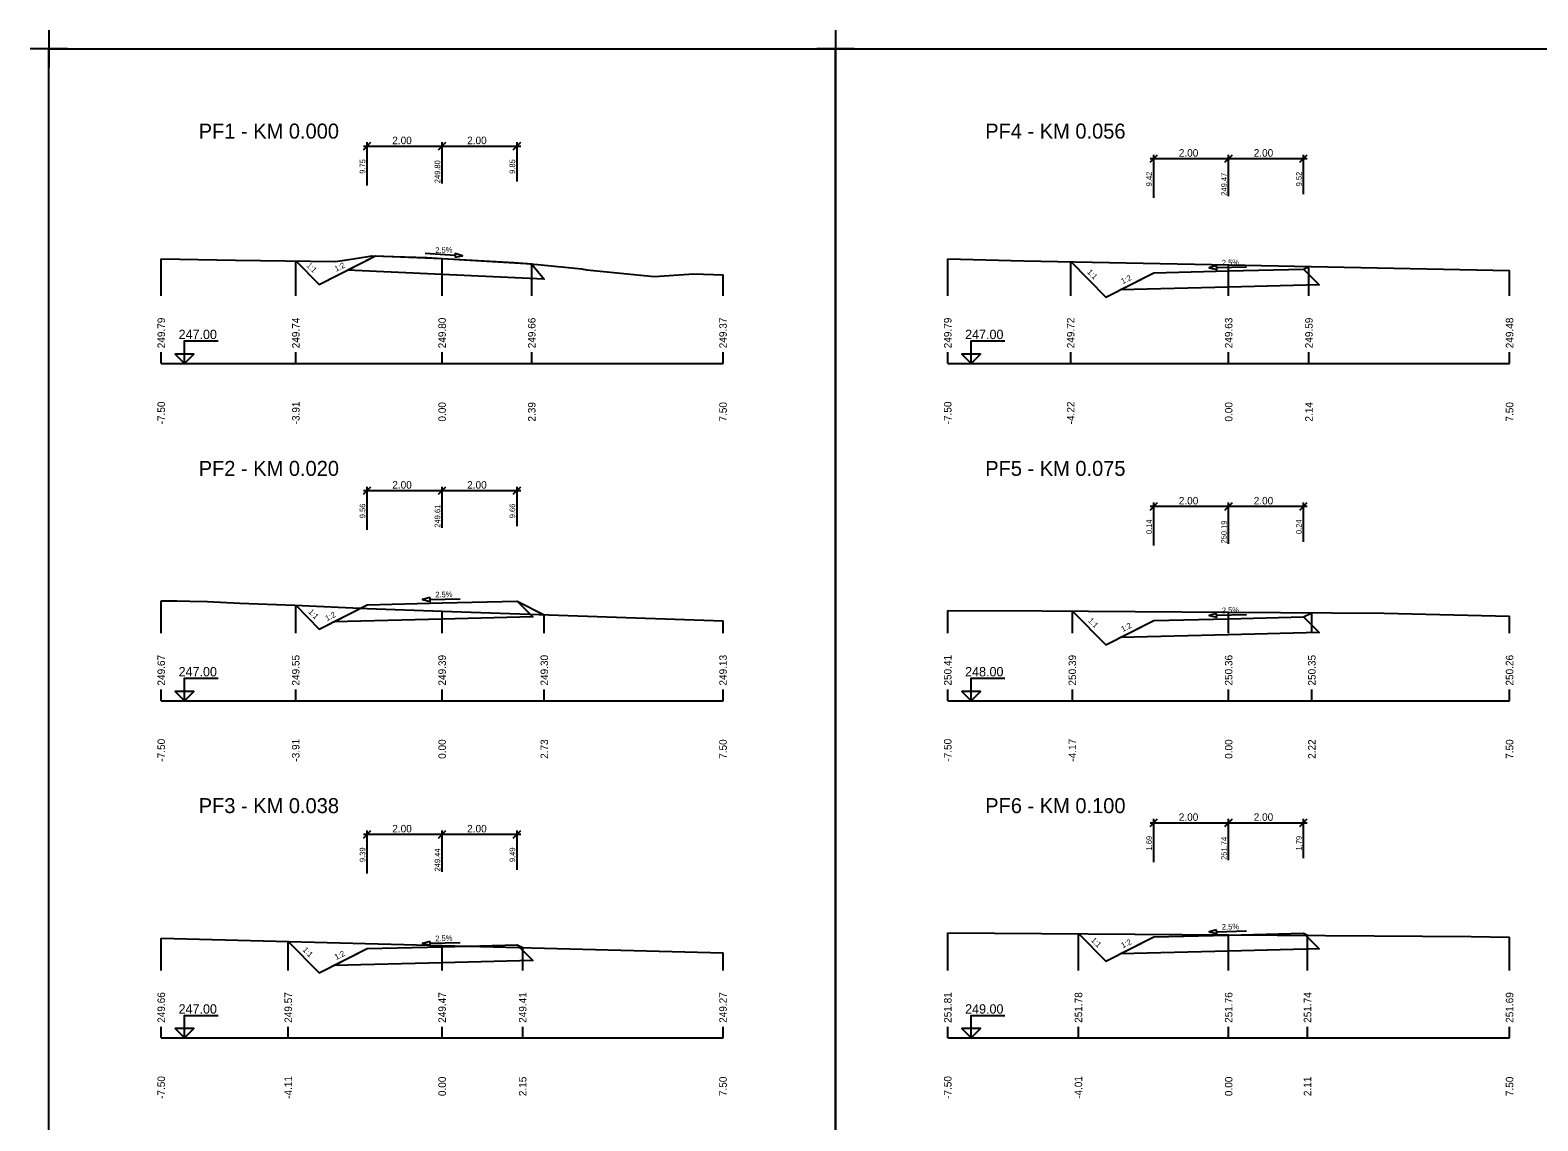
# Model space of a CAD drawing. Extents: x -1895 to 2525, y -19 to 585.
# Drawn here: x -1894.9 to -1492.4, y 293.9 to 584.9 of the extents above; entities that cross this region are included whole.
import ezdxf

# ---------------------------------------------------------------- set-up
doc = ezdxf.new("R2010")
doc.units = 0
for name, color, linetype in [('KOTA', 7, 'Continuous'), ('KOTA_DELKY', 7, 'Continuous'), ('KOTA_DELKY_CONT', 7, 'Continuous'), ('NS_TELESO_VOZOVKY', 7, 'Continuous'), ('NS_V_PF', 7, 'Continuous'), ('REZY_PF_PUVODNI', 7, 'Continuous'), ('SESTAVY_REZU_PF', 7, 'Continuous'), ('SKLON', 7, 'Continuous'), ('SVK', 7, 'Continuous')]:
    doc.layers.add(name, color=color, linetype=linetype)

msp = doc.modelspace()

# ---------------------------------------------------------------- linework, layer by layer
for p, q in [((-1889.95, 584.93), (-1889.95, 574.93)), ((-1889.95, 584.93), (-1889.95, 574.93)), ((-1679.95, 584.93), (-1679.95, 574.93)), ((-1679.95, 584.93), (-1679.95, 574.93)), ((-1884.95, 579.93), (-1894.95, 579.93)), ((-1884.95, 579.93), (-1894.95, 579.93)), ((-1674.95, 579.93), (-1684.95, 579.93)), ((-1674.95, 579.93), (-1684.95, 579.93))]:
    msp.add_line(p, q)
for points in [[(-1889.95, 579.93), (-1679.95, 579.93), (-1679.95, 282.93), (-1889.95, 282.93)], [(-1679.95, 579.93), (-1469.95, 579.93), (-1469.95, 282.93), (-1679.95, 282.93)]]:
    msp.add_lwpolyline(points, close=True)
at = {"layer": 'KOTA'}
for points in [[(-1853.73, 498.5), (-1856.23, 498.5), (-1853.73, 496), (-1853.73, 502), (-1844.73, 502)], [(-1643.73, 498.5), (-1646.23, 498.5), (-1643.73, 496), (-1643.73, 502), (-1634.73, 502)], [(-1853.73, 496), (-1851.23, 498.5), (-1853.73, 498.5)], [(-1643.73, 496), (-1641.23, 498.5), (-1643.73, 498.5)], [(-1853.73, 408.5), (-1856.23, 408.5), (-1853.73, 406), (-1853.73, 412), (-1844.73, 412)], [(-1643.73, 408.5), (-1646.23, 408.5), (-1643.73, 406), (-1643.73, 412), (-1634.73, 412)], [(-1853.73, 406), (-1851.23, 408.5), (-1853.73, 408.5)], [(-1643.73, 406), (-1641.23, 408.5), (-1643.73, 408.5)], [(-1853.73, 318.5), (-1856.23, 318.5), (-1853.73, 316), (-1853.73, 322), (-1844.73, 322)], [(-1853.73, 316), (-1851.23, 318.5), (-1853.73, 318.5)], [(-1643.73, 318.5), (-1646.23, 318.5), (-1643.73, 316), (-1643.73, 322), (-1634.73, 322)], [(-1643.73, 316), (-1641.23, 318.5), (-1643.73, 318.5)]]:
    msp.add_lwpolyline(points, dxfattribs=at)
at = {"layer": 'KOTA_DELKY'}
for points in [[(-1805.95, 553.01), (-1803.95, 555.01)], [(-1805.95, 554.01), (-1783.95, 554.01)], [(-1804.95, 543.51), (-1804.95, 555.01)], [(-1785.95, 553.01), (-1783.95, 555.01)], [(-1785.95, 553.01), (-1783.95, 555.01)], [(-1785.95, 554.01), (-1763.95, 554.01)], [(-1784.95, 544.01), (-1784.95, 555.01)], [(-1784.95, 544.01), (-1784.95, 555.01)], [(-1765.95, 553.01), (-1763.95, 555.01)], [(-1764.95, 544.51), (-1764.95, 555.01)], [(-1595.95, 549.68), (-1593.95, 551.68)], [(-1594.95, 540.18), (-1594.95, 551.68)], [(-1575.95, 549.68), (-1573.95, 551.68)], [(-1575.95, 549.68), (-1573.95, 551.68)], [(-1574.95, 540.68), (-1574.95, 551.68)], [(-1574.95, 540.68), (-1574.95, 551.68)], [(-1555.95, 549.68), (-1553.95, 551.68)], [(-1554.95, 541.18), (-1554.95, 551.68)], [(-1595.95, 550.68), (-1573.95, 550.68)], [(-1575.95, 550.68), (-1553.95, 550.68)], [(-1805.95, 461.1), (-1803.95, 463.1)], [(-1804.95, 451.6), (-1804.95, 463.1)], [(-1785.95, 461.1), (-1783.95, 463.1)], [(-1785.95, 461.1), (-1783.95, 463.1)], [(-1784.95, 452.1), (-1784.95, 463.1)], [(-1784.95, 452.1), (-1784.95, 463.1)], [(-1765.95, 461.1), (-1763.95, 463.1)], [(-1764.95, 452.6), (-1764.95, 463.1)], [(-1805.95, 462.1), (-1783.95, 462.1)], [(-1785.95, 462.1), (-1763.95, 462.1)], [(-1595.95, 456.88), (-1593.95, 458.88)], [(-1595.95, 457.88), (-1573.95, 457.88)], [(-1594.95, 447.38), (-1594.95, 458.88)], [(-1575.95, 456.88), (-1573.95, 458.88)], [(-1575.95, 456.88), (-1573.95, 458.88)], [(-1575.95, 457.88), (-1553.95, 457.88)], [(-1574.95, 447.88), (-1574.95, 458.88)], [(-1574.95, 447.88), (-1574.95, 458.88)], [(-1555.95, 456.88), (-1553.95, 458.88)], [(-1554.95, 448.38), (-1554.95, 458.88)], [(-1595.95, 372.45), (-1593.95, 374.45)], [(-1594.95, 362.95), (-1594.95, 374.45)], [(-1575.95, 372.45), (-1573.95, 374.45)], [(-1575.95, 372.45), (-1573.95, 374.45)], [(-1574.95, 363.45), (-1574.95, 374.45)], [(-1574.95, 363.45), (-1574.95, 374.45)], [(-1555.95, 372.45), (-1553.95, 374.45)], [(-1554.95, 363.95), (-1554.95, 374.45)], [(-1805.95, 369.36), (-1803.95, 371.36)], [(-1805.95, 370.36), (-1783.95, 370.36)], [(-1804.95, 359.86), (-1804.95, 371.36)], [(-1785.95, 369.36), (-1783.95, 371.36)], [(-1785.95, 369.36), (-1783.95, 371.36)], [(-1785.95, 370.36), (-1763.95, 370.36)], [(-1784.95, 360.36), (-1784.95, 371.36)], [(-1784.95, 360.36), (-1784.95, 371.36)], [(-1765.95, 369.36), (-1763.95, 371.36)], [(-1764.95, 360.86), (-1764.95, 371.36)], [(-1595.95, 373.45), (-1573.95, 373.45)], [(-1575.95, 373.45), (-1553.95, 373.45)]]:
    msp.add_lwpolyline(points, dxfattribs=at)
at = {"layer": 'NS_TELESO_VOZOVKY'}
for points in [[(-1784.95, 524.01), (-1761.06, 522.58), (-1761.06, 522.58), (-1757.74, 518.46), (-1784.95, 519.71), (-1810.25, 520.86), (-1802.75, 524.69), (-1802.75, 524.69), (-1784.95, 524.01)], [(-1574.95, 520.68), (-1554.95, 521.18), (-1554.95, 521.18), (-1550.75, 516.98), (-1574.95, 516.38), (-1603.89, 515.65), (-1594.95, 520.18), (-1594.95, 520.18), (-1574.95, 520.68)], [(-1784.95, 432.1), (-1764.95, 432.6), (-1764.95, 432.6), (-1760.75, 428.4), (-1784.95, 427.8), (-1813.89, 427.08), (-1804.95, 431.6), (-1804.95, 431.6), (-1784.95, 432.1)], [(-1574.95, 427.88), (-1554.95, 428.38), (-1554.95, 428.38), (-1550.75, 424.19), (-1574.95, 423.58), (-1603.89, 422.86), (-1594.95, 427.38), (-1594.95, 427.38), (-1574.95, 427.88)], [(-1574.95, 343.45), (-1554.95, 343.95), (-1554.95, 343.95), (-1550.75, 339.75), (-1574.95, 339.15), (-1603.89, 338.43), (-1594.95, 342.95), (-1594.95, 342.95), (-1574.95, 343.45)], [(-1784.95, 340.36), (-1764.95, 340.86), (-1764.95, 340.86), (-1760.75, 336.66), (-1784.95, 336.06), (-1813.89, 335.34), (-1804.95, 339.86), (-1804.95, 339.86), (-1784.95, 340.36)]]:
    msp.add_lwpolyline(points, dxfattribs=at)
at = {"layer": 'NS_V_PF'}
for points in [[(-1824.01, 523.35), (-1817.76, 517.04), (-1802.75, 524.69), (-1802.75, 524.69), (-1784.95, 524.01), (-1765.74, 522.97), (-1765.74, 522.97), (-1761.02, 522.55)], [(-1617.13, 523.17), (-1607.76, 513.7), (-1594.95, 520.18), (-1594.95, 520.18), (-1574.95, 520.68), (-1554.95, 521.18), (-1554.95, 521.18), (-1553.52, 521.89)], [(-1824.04, 431.46), (-1817.76, 425.12), (-1804.95, 431.6), (-1804.95, 431.6), (-1784.95, 432.1), (-1764.95, 432.6), (-1764.95, 432.6), (-1757.67, 428.96)], [(-1616.69, 429.93), (-1607.76, 420.9), (-1594.95, 427.38), (-1594.95, 427.38), (-1574.95, 427.88), (-1554.95, 428.38), (-1554.95, 428.38), (-1552.74, 429.49)], [(-1615.06, 343.84), (-1607.76, 336.47), (-1594.95, 342.95), (-1594.95, 342.95), (-1574.95, 343.45), (-1554.95, 343.95), (-1554.95, 343.95), (-1553.89, 343.42)], [(-1826.04, 341.75), (-1817.76, 333.38), (-1804.95, 339.86), (-1804.95, 339.86), (-1784.95, 340.36), (-1764.95, 340.86), (-1764.95, 340.86), (-1763.44, 340.11)]]:
    msp.add_lwpolyline(points, dxfattribs=at)
at = {"layer": 'REZY_PF_PUVODNI'}
for points in [[(-1859.95, 523.88), (-1840.11, 523.52), (-1813.43, 523.24), (-1808.08, 523.99), (-1803.74, 524.74), (-1789.08, 524.24), (-1784.95, 524.01), (-1765.74, 522.97), (-1759.43, 522.41), (-1747.75, 521.26), (-1746.32, 521.01), (-1728.38, 519.24), (-1717.72, 519.9), (-1709.95, 519.67)], [(-1649.95, 523.92), (-1629.68, 523.42), (-1574.95, 522.32), (-1499.95, 520.82)], [(-1859.95, 432.68), (-1855.79, 432.61), (-1852.29, 432.53), (-1847.59, 432.45), (-1838.96, 432.04), (-1824.3, 431.48), (-1804.93, 430.62), (-1784.95, 429.92), (-1709.95, 427.28)], [(-1649.95, 430.07), (-1624.86, 429.99), (-1574.95, 429.64), (-1533.46, 429.35), (-1499.95, 428.59)], [(-1859.95, 342.64), (-1784.95, 340.67), (-1709.95, 338.7)], [(-1649.95, 344.09), (-1574.95, 343.57), (-1510.19, 343.12), (-1499.95, 342.89)]]:
    msp.add_lwpolyline(points, dxfattribs=at)
at = {"layer": 'SESTAVY_REZU_PF'}
for points in [[(-1859.95, 496), (-1709.95, 496)], [(-1649.95, 496), (-1499.95, 496)], [(-1859.95, 406), (-1709.95, 406)], [(-1649.95, 406), (-1499.95, 406)], [(-1859.95, 316), (-1709.95, 316)], [(-1649.95, 316), (-1499.95, 316)]]:
    msp.add_lwpolyline(points, dxfattribs=at)
at = {"layer": 'SKLON'}
for points in [[(-1781.48, 524.84), (-1789.47, 525.33)], [(-1781.51, 524.34), (-1779.49, 524.72), (-1781.45, 525.34), (-1781.51, 524.34)], [(-1578.16, 522.1), (-1580.15, 521.55), (-1578.14, 521.1), (-1578.16, 522.1)], [(-1578.15, 521.6), (-1570.15, 521.8)], [(-1788.16, 433.52), (-1790.15, 432.97), (-1788.14, 432.52), (-1788.16, 433.52)], [(-1788.15, 433.02), (-1780.15, 433.22)], [(-1578.16, 429.3), (-1580.15, 428.75), (-1578.14, 428.3), (-1578.16, 429.3)], [(-1578.15, 428.8), (-1570.15, 429)], [(-1578.16, 344.87), (-1580.15, 344.32), (-1578.14, 343.87), (-1578.16, 344.87)], [(-1578.15, 344.37), (-1570.15, 344.57)], [(-1788.16, 341.78), (-1790.15, 341.23), (-1788.14, 340.78), (-1788.16, 341.78)], [(-1788.15, 341.28), (-1780.15, 341.48)]]:
    msp.add_lwpolyline(points, dxfattribs=at)
at = {"layer": 'SVK'}
for points in [[(-1859.95, 514), (-1859.95, 523.88)], [(-1824.01, 514), (-1824.01, 523.35)], [(-1784.95, 514), (-1784.95, 524.01)], [(-1649.95, 514), (-1649.95, 523.92)], [(-1761.02, 514), (-1761.02, 522.55)], [(-1709.95, 514), (-1709.95, 519.67)], [(-1617.13, 514), (-1617.13, 523.17)], [(-1574.95, 514), (-1574.95, 522.32)], [(-1553.52, 514), (-1553.52, 521.89)], [(-1499.95, 514), (-1499.95, 520.82)], [(-1859.95, 496), (-1859.95, 499)], [(-1824.01, 496), (-1824.01, 499)], [(-1784.95, 496), (-1784.95, 499)], [(-1761.02, 496), (-1761.02, 499)], [(-1709.95, 496), (-1709.95, 499)], [(-1649.95, 496), (-1649.95, 499)], [(-1617.13, 496), (-1617.13, 499)], [(-1574.95, 496), (-1574.95, 499)], [(-1553.52, 496), (-1553.52, 499)], [(-1499.95, 496), (-1499.95, 499)], [(-1859.95, 424), (-1859.95, 432.68)], [(-1824.04, 424), (-1824.04, 431.46)], [(-1784.95, 424), (-1784.95, 429.92)], [(-1757.67, 424), (-1757.67, 428.96)], [(-1709.95, 424), (-1709.95, 427.28)], [(-1649.95, 424), (-1649.95, 430.07)], [(-1616.69, 424), (-1616.69, 429.93)], [(-1574.95, 424), (-1574.95, 429.64)], [(-1552.74, 424), (-1552.74, 429.49)], [(-1499.95, 424), (-1499.95, 428.59)], [(-1859.95, 406), (-1859.95, 409)], [(-1824.04, 406), (-1824.04, 409)], [(-1784.95, 406), (-1784.95, 409)], [(-1757.67, 406), (-1757.67, 409)], [(-1709.95, 406), (-1709.95, 409)], [(-1649.95, 406), (-1649.95, 409)], [(-1616.69, 406), (-1616.69, 409)], [(-1574.95, 406), (-1574.95, 409)], [(-1552.74, 406), (-1552.74, 409)], [(-1499.95, 406), (-1499.95, 409)], [(-1859.95, 334), (-1859.95, 342.64)], [(-1649.95, 334), (-1649.95, 344.09)], [(-1615.06, 334), (-1615.06, 343.84)], [(-1574.95, 334), (-1574.95, 343.57)], [(-1553.89, 334), (-1553.89, 343.42)], [(-1499.95, 334), (-1499.95, 342.89)], [(-1826.04, 334), (-1826.04, 341.75)], [(-1784.95, 334), (-1784.95, 340.67)], [(-1763.44, 334), (-1763.44, 340.11)], [(-1709.95, 334), (-1709.95, 338.7)], [(-1859.95, 316), (-1859.95, 319)], [(-1826.04, 316), (-1826.04, 319)], [(-1784.95, 316), (-1784.95, 319)], [(-1763.44, 316), (-1763.44, 319)], [(-1709.95, 316), (-1709.95, 319)], [(-1649.95, 316), (-1649.95, 319)], [(-1615.06, 316), (-1615.06, 319)], [(-1574.95, 316), (-1574.95, 319)], [(-1553.89, 316), (-1553.89, 319)], [(-1499.95, 316), (-1499.95, 319)]]:
    msp.add_lwpolyline(points, dxfattribs=at)

# ---------------------------------------------------------------- texts
at = {"layer": 'KOTA'}
for s, p in [('247.00', (-1855.31, 502.5)), ('247.00', (-1645.31, 502.5)), ('247.00', (-1855.31, 412.5)), ('248.00', (-1645.31, 412.5)), ('247.00', (-1855.31, 322.5)), ('249.00', (-1645.31, 322.5))]:
    msp.add_text(s, height=2.5, dxfattribs=at).set_placement(p)
at = {"layer": 'KOTA_DELKY'}
for p in [(-1798.26, 554.51), (-1778.26, 554.51), (-1588.26, 551.18), (-1568.26, 551.18), (-1798.26, 462.6), (-1778.26, 462.6), (-1588.26, 458.38), (-1568.26, 458.38), (-1588.26, 373.95), (-1568.26, 373.95), (-1798.26, 370.86), (-1778.26, 370.86)]:
    msp.add_text('2.00', height=2, dxfattribs=at).set_placement(p)
at = {"layer": 'KOTA_DELKY_CONT'}
for s, p in [('9.75', (-1805.45, 546.6)), ('249.80', (-1785.45, 544.09)), ('9.85', (-1765.45, 546.6)), ('9.42', (-1595.45, 543.26)), ('249.47', (-1575.45, 540.75)), ('9.52', (-1555.45, 543.26)), ('9.56', (-1805.45, 454.69)), ('249.61', (-1785.45, 452.18)), ('9.66', (-1765.45, 454.69)), ('0.14', (-1595.45, 450.47)), ('250.19', (-1575.45, 447.96)), ('0.24', (-1555.45, 450.47)), ('9.39', (-1805.45, 362.95)), ('249.44', (-1785.45, 360.44)), ('9.49', (-1765.45, 362.95)), ('1.69', (-1595.45, 366.04)), ('251.74', (-1575.45, 363.53)), ('1.79', (-1555.45, 366.04))]:
    msp.add_text(s, height=1.5, rotation=90, dxfattribs=at).set_placement(p)
at = {"layer": 'SESTAVY_REZU_PF'}
for s, p in [('PF1 - KM 0.000', (-1849.95, 556)), ('PF4 - KM 0.056', (-1639.95, 556)), ('PF2 - KM 0.020', (-1849.95, 466)), ('PF5 - KM 0.075', (-1639.95, 466)), ('PF3 - KM 0.038', (-1849.95, 376)), ('PF6 - KM 0.100', (-1639.95, 376))]:
    msp.add_text(s, height=4, dxfattribs=at).set_placement(p)
at = {"layer": 'SKLON'}
for s, rotation, p in [('2.5%', 1.4321, (-1786.75, 525.47)), ('2.5%', 1.4321, (-1576.75, 522.13)), ('1:1', 314.7121, (-1821.28, 522.02)), ('1:2', 26.8233, (-1813.21, 520.46)), ('1:1', 314.7121, (-1612.84, 520.26)), ('1:2', 26.8233, (-1603.21, 517.12)), ('2.5%', 1.4321, (-1786.75, 433.55)), ('2.5%', 1.4321, (-1576.75, 429.34)), ('1:1', 314.7121, (-1820.77, 429.59)), ('1:2', 26.8233, (-1815.7, 427.21)), ('1:1', 314.7121, (-1612.62, 427.24)), ('1:2', 26.8233, (-1603.21, 424.32)), ('2.5%', 1.4321, (-1576.75, 344.9)), ('2.5%', 1.4321, (-1786.75, 341.81)), ('1:1', 314.7121, (-1611.8, 341.98)), ('1:2', 26.8233, (-1603.21, 339.89)), ('1:1', 314.7121, (-1822.3, 339.39)), ('1:2', 26.8233, (-1813.21, 336.8))]:
    msp.add_text(s, height=1.5, rotation=rotation, dxfattribs=at).set_placement(p)
at = {"layer": 'SVK'}
for s, p in [(' 249.79', (-1858.95, 499.3)), (' 249.74', (-1823.01, 499.3)), (' 249.80', (-1783.95, 499.3)), (' 249.66', (-1760.02, 499.3)), (' 249.37', (-1708.95, 499.3)), (' 249.79', (-1648.95, 499.3)), (' 249.72', (-1616.13, 499.3)), (' 249.63', (-1573.95, 499.3)), (' 249.59', (-1552.52, 499.3)), (' 249.48', (-1498.95, 499.3)), (' -7.50', (-1858.95, 479)), (' -3.91', (-1823.01, 479)), ('  0.00', (-1783.95, 479)), ('  2.39', (-1760.02, 479)), ('  7.50', (-1708.95, 479)), (' -7.50', (-1648.95, 479)), (' -4.22', (-1616.13, 479)), ('  0.00', (-1573.95, 479)), ('  2.14', (-1552.52, 479)), ('  7.50', (-1498.95, 479)), (' 249.67', (-1858.95, 409.3)), (' 249.55', (-1823.04, 409.3)), (' 249.39', (-1783.95, 409.3)), (' 249.30', (-1756.67, 409.3)), (' 249.13', (-1708.95, 409.3)), (' 250.41', (-1648.95, 409.3)), (' 250.39', (-1615.69, 409.3)), (' 250.36', (-1573.95, 409.3)), (' 250.35', (-1551.74, 409.3)), (' 250.26', (-1498.95, 409.3)), (' -7.50', (-1858.95, 389)), (' -3.91', (-1823.04, 389)), ('  0.00', (-1783.95, 389)), ('  2.73', (-1756.67, 389)), ('  7.50', (-1708.95, 389)), (' -7.50', (-1648.95, 389)), (' -4.17', (-1615.69, 389)), ('  0.00', (-1573.95, 389)), ('  2.22', (-1551.74, 389)), ('  7.50', (-1498.95, 389)), (' 249.66', (-1858.95, 319.3)), (' 249.57', (-1825.04, 319.3)), (' 249.47', (-1783.95, 319.3)), (' 249.41', (-1762.44, 319.3)), (' 249.27', (-1708.95, 319.3)), (' 251.81', (-1648.95, 319.3)), (' 251.78', (-1614.06, 319.3)), (' 251.76', (-1573.95, 319.3)), (' 251.74', (-1552.89, 319.3)), (' 251.69', (-1498.95, 319.3)), (' -7.50', (-1858.95, 299)), (' -4.11', (-1825.04, 299)), ('  0.00', (-1783.95, 299)), ('  2.15', (-1762.44, 299)), ('  7.50', (-1708.95, 299)), (' -7.50', (-1648.95, 299)), (' -4.01', (-1614.06, 299)), ('  0.00', (-1573.95, 299)), ('  2.11', (-1552.89, 299)), ('  7.50', (-1498.95, 299))]:
    msp.add_text(s, height=2, rotation=90, dxfattribs=at).set_placement(p)

doc.saveas('drawing.dxf')
